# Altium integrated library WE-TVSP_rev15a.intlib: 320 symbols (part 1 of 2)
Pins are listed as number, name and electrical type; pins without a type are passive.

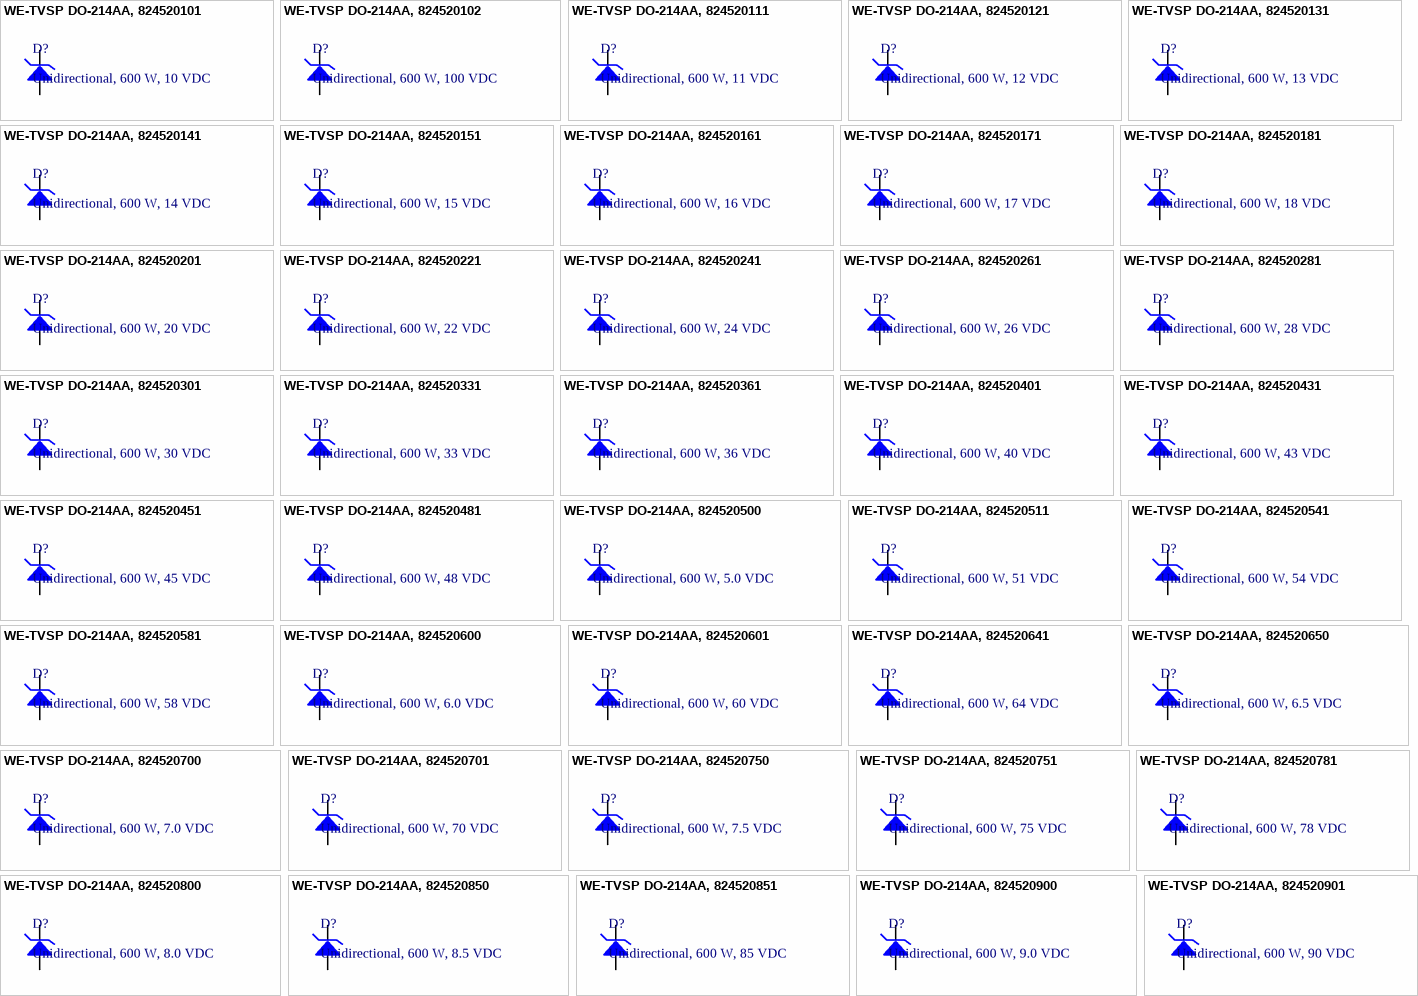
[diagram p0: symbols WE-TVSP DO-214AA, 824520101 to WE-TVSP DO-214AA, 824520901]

## WE-TVSP DO-214AA, 824520101
designator D?, comment Unidirectional, 600 W, 10 VDC
WE-TVSP Power TVS Diode, Unidirectional, 600 W, 10 VDC; partNo: 824520101; Manufacturer: Wurth Elektronik
footprint DO-214AA_Unidirectional
pins: 1, 2

## WE-TVSP DO-214AA, 824520102
designator D?, comment Unidirectional, 600 W, 100 VDC
WE-TVSP Power TVS Diode, Unidirectional, 600 W, 100 VDC; partNo: 824520102; Manufacturer: Wurth Elektronik
footprint DO-214AA_Unidirectional
pins: 1, 2

## WE-TVSP DO-214AA, 824520111
designator D?, comment Unidirectional, 600 W, 11 VDC
WE-TVSP Power TVS Diode, Unidirectional, 600 W, 11 VDC; partNo: 824520111; Manufacturer: Wurth Elektronik
footprint DO-214AA_Unidirectional
pins: 1, 2

## WE-TVSP DO-214AA, 824520121
designator D?, comment Unidirectional, 600 W, 12 VDC
WE-TVSP Power TVS Diode, Unidirectional, 600 W, 12 VDC; partNo: 824520121; Manufacturer: Wurth Elektronik
footprint DO-214AA_Unidirectional
pins: 1, 2

## WE-TVSP DO-214AA, 824520131
designator D?, comment Unidirectional, 600 W, 13 VDC
WE-TVSP Power TVS Diode, Unidirectional, 600 W, 13 VDC; partNo: 824520131; Manufacturer: Wurth Elektronik
footprint DO-214AA_Unidirectional
pins: 1, 2

## WE-TVSP DO-214AA, 824520141
designator D?, comment Unidirectional, 600 W, 14 VDC
WE-TVSP Power TVS Diode, Unidirectional, 600 W, 14 VDC; partNo: 824520141; Manufacturer: Wurth Elektronik
footprint DO-214AA_Unidirectional
pins: 1, 2

## WE-TVSP DO-214AA, 824520151
designator D?, comment Unidirectional, 600 W, 15 VDC
WE-TVSP Power TVS Diode, Unidirectional, 600 W, 15 VDC; partNo: 824520151; Manufacturer: Wurth Elektronik
footprint DO-214AA_Unidirectional
pins: 1, 2

## WE-TVSP DO-214AA, 824520161
designator D?, comment Unidirectional, 600 W, 16 VDC
WE-TVSP Power TVS Diode, Unidirectional, 600 W, 16 VDC; partNo: 824520161; Manufacturer: Wurth Elektronik
footprint DO-214AA_Unidirectional
pins: 1, 2

## WE-TVSP DO-214AA, 824520171
designator D?, comment Unidirectional, 600 W, 17 VDC
WE-TVSP Power TVS Diode, Unidirectional, 600 W, 17 VDC; partNo: 824520171; Manufacturer: Wurth Elektronik
footprint DO-214AA_Unidirectional
pins: 1, 2

## WE-TVSP DO-214AA, 824520181
designator D?, comment Unidirectional, 600 W, 18 VDC
WE-TVSP Power TVS Diode, Unidirectional, 600 W, 18 VDC; partNo: 824520181; Manufacturer: Wurth Elektronik
footprint DO-214AA_Unidirectional
pins: 1, 2

## WE-TVSP DO-214AA, 824520201
designator D?, comment Unidirectional, 600 W, 20 VDC
WE-TVSP Power TVS Diode, Unidirectional, 600 W, 20 VDC; partNo: 824520201; Manufacturer: Wurth Elektronik
footprint DO-214AA_Unidirectional
pins: 1, 2

## WE-TVSP DO-214AA, 824520221
designator D?, comment Unidirectional, 600 W, 22 VDC
WE-TVSP Power TVS Diode, Unidirectional, 600 W, 22 VDC; partNo: 824520221; Manufacturer: Wurth Elektronik
footprint DO-214AA_Unidirectional
pins: 1, 2

## WE-TVSP DO-214AA, 824520241
designator D?, comment Unidirectional, 600 W, 24 VDC
WE-TVSP Power TVS Diode, Unidirectional, 600 W, 24 VDC; partNo: 824520241; Manufacturer: Wurth Elektronik
footprint DO-214AA_Unidirectional
pins: 1, 2

## WE-TVSP DO-214AA, 824520261
designator D?, comment Unidirectional, 600 W, 26 VDC
WE-TVSP Power TVS Diode, Unidirectional, 600 W, 26 VDC; partNo: 824520261; Manufacturer: Wurth Elektronik
footprint DO-214AA_Unidirectional
pins: 1, 2

## WE-TVSP DO-214AA, 824520281
designator D?, comment Unidirectional, 600 W, 28 VDC
WE-TVSP Power TVS Diode, Unidirectional, 600 W, 28 VDC; partNo: 824520281; Manufacturer: Wurth Elektronik
footprint DO-214AA_Unidirectional
pins: 1, 2

## WE-TVSP DO-214AA, 824520301
designator D?, comment Unidirectional, 600 W, 30 VDC
WE-TVSP Power TVS Diode, Unidirectional, 600 W, 30 VDC; partNo: 824520301; Manufacturer: Wurth Elektronik
footprint DO-214AA_Unidirectional
pins: 1, 2

## WE-TVSP DO-214AA, 824520331
designator D?, comment Unidirectional, 600 W, 33 VDC
WE-TVSP Power TVS Diode, Unidirectional, 600 W, 33 VDC; partNo: 824520331; Manufacturer: Wurth Elektronik
footprint DO-214AA_Unidirectional
pins: 1, 2

## WE-TVSP DO-214AA, 824520361
designator D?, comment Unidirectional, 600 W, 36 VDC
WE-TVSP Power TVS Diode, Unidirectional, 600 W, 36 VDC; partNo: 824520361; Manufacturer: Wurth Elektronik
footprint DO-214AA_Unidirectional
pins: 1, 2

## WE-TVSP DO-214AA, 824520401
designator D?, comment Unidirectional, 600 W, 40 VDC
WE-TVSP Power TVS Diode, Unidirectional, 600 W, 40 VDC; partNo: 824520401; Manufacturer: Wurth Elektronik
footprint DO-214AA_Unidirectional
pins: 1, 2

## WE-TVSP DO-214AA, 824520431
designator D?, comment Unidirectional, 600 W, 43 VDC
WE-TVSP Power TVS Diode, Unidirectional, 600 W, 43 VDC; partNo: 824520431; Manufacturer: Wurth Elektronik
footprint DO-214AA_Unidirectional
pins: 1, 2

## WE-TVSP DO-214AA, 824520451
designator D?, comment Unidirectional, 600 W, 45 VDC
WE-TVSP Power TVS Diode, Unidirectional, 600 W, 45 VDC; partNo: 824520451; Manufacturer: Wurth Elektronik
footprint DO-214AA_Unidirectional
pins: 1, 2

## WE-TVSP DO-214AA, 824520481
designator D?, comment Unidirectional, 600 W, 48 VDC
WE-TVSP Power TVS Diode, Unidirectional, 600 W, 48 VDC; partNo: 824520481; Manufacturer: Wurth Elektronik
footprint DO-214AA_Unidirectional
pins: 1, 2

## WE-TVSP DO-214AA, 824520500
designator D?, comment Unidirectional, 600 W, 5.0 VDC
WE-TVSP Power TVS Diode, Unidirectional, 600 W, 5.0 VDC; partNo: 824520500; Manufacturer: Wurth Elektronik
footprint DO-214AA_Unidirectional
pins: 1, 2

## WE-TVSP DO-214AA, 824520511
designator D?, comment Unidirectional, 600 W, 51 VDC
WE-TVSP Power TVS Diode, Unidirectional, 600 W, 51 VDC; partNo: 824520511; Manufacturer: Wurth Elektronik
footprint DO-214AA_Unidirectional
pins: 1, 2

## WE-TVSP DO-214AA, 824520541
designator D?, comment Unidirectional, 600 W, 54 VDC
WE-TVSP Power TVS Diode, Unidirectional, 600 W, 54 VDC; partNo: 824520541; Manufacturer: Wurth Elektronik
footprint DO-214AA_Unidirectional
pins: 1, 2

## WE-TVSP DO-214AA, 824520581
designator D?, comment Unidirectional, 600 W, 58 VDC
WE-TVSP Power TVS Diode, Unidirectional, 600 W, 58 VDC; partNo: 824520581; Manufacturer: Wurth Elektronik
footprint DO-214AA_Unidirectional
pins: 1, 2

## WE-TVSP DO-214AA, 824520600
designator D?, comment Unidirectional, 600 W, 6.0 VDC
WE-TVSP Power TVS Diode, Unidirectional, 600 W, 6.0 VDC; partNo: 824520600; Manufacturer: Wurth Elektronik
footprint DO-214AA_Unidirectional
pins: 1, 2

## WE-TVSP DO-214AA, 824520601
designator D?, comment Unidirectional, 600 W, 60 VDC
WE-TVSP Power TVS Diode, Unidirectional, 600 W, 60 VDC; partNo: 824520601; Manufacturer: Wurth Elektronik
footprint DO-214AA_Unidirectional
pins: 1, 2

## WE-TVSP DO-214AA, 824520641
designator D?, comment Unidirectional, 600 W, 64 VDC
WE-TVSP Power TVS Diode, Unidirectional, 600 W, 64 VDC; partNo: 824520641; Manufacturer: Wurth Elektronik
footprint DO-214AA_Unidirectional
pins: 1, 2

## WE-TVSP DO-214AA, 824520650
designator D?, comment Unidirectional, 600 W, 6.5 VDC
WE-TVSP Power TVS Diode, Unidirectional, 600 W, 6.5 VDC; partNo: 824520650; Manufacturer: Wurth Elektronik
footprint DO-214AA_Unidirectional
pins: 1, 2

## WE-TVSP DO-214AA, 824520700
designator D?, comment Unidirectional, 600 W, 7.0 VDC
WE-TVSP Power TVS Diode, Unidirectional, 600 W, 7.0 VDC; partNo: 824520700; Manufacturer: Wurth Elektronik
footprint DO-214AA_Unidirectional
pins: 1, 2

## WE-TVSP DO-214AA, 824520701
designator D?, comment Unidirectional, 600 W, 70 VDC
WE-TVSP Power TVS Diode, Unidirectional, 600 W, 70 VDC; partNo: 824520701; Manufacturer: Wurth Elektronik
footprint DO-214AA_Unidirectional
pins: 1, 2

## WE-TVSP DO-214AA, 824520750
designator D?, comment Unidirectional, 600 W, 7.5 VDC
WE-TVSP Power TVS Diode, Unidirectional, 600 W, 7.5 VDC; partNo: 824520750; Manufacturer: Wurth Elektronik
footprint DO-214AA_Unidirectional
pins: 1, 2

## WE-TVSP DO-214AA, 824520751
designator D?, comment Unidirectional, 600 W, 75 VDC
WE-TVSP Power TVS Diode, Unidirectional, 600 W, 75 VDC; partNo: 824520751; Manufacturer: Wurth Elektronik
footprint DO-214AA_Unidirectional
pins: 1, 2

## WE-TVSP DO-214AA, 824520781
designator D?, comment Unidirectional, 600 W, 78 VDC
WE-TVSP Power TVS Diode, Unidirectional, 600 W, 78 VDC; partNo: 824520781; Manufacturer: Wurth Elektronik
footprint DO-214AA_Unidirectional
pins: 1, 2

## WE-TVSP DO-214AA, 824520800
designator D?, comment Unidirectional, 600 W, 8.0 VDC
WE-TVSP Power TVS Diode, Unidirectional, 600 W, 8.0 VDC; partNo: 824520800; Manufacturer: Wurth Elektronik
footprint DO-214AA_Unidirectional
pins: 1, 2

## WE-TVSP DO-214AA, 824520850
designator D?, comment Unidirectional, 600 W, 8.5 VDC
WE-TVSP Power TVS Diode, Unidirectional, 600 W, 8.5 VDC; partNo: 824520850; Manufacturer: Wurth Elektronik
footprint DO-214AA_Unidirectional
pins: 1, 2

## WE-TVSP DO-214AA, 824520851
designator D?, comment Unidirectional, 600 W, 85 VDC
WE-TVSP Power TVS Diode, Unidirectional, 600 W, 85 VDC; partNo: 824520851; Manufacturer: Wurth Elektronik
footprint DO-214AA_Unidirectional
pins: 1, 2

## WE-TVSP DO-214AA, 824520900
designator D?, comment Unidirectional, 600 W, 9.0 VDC
WE-TVSP Power TVS Diode, Unidirectional, 600 W, 9.0 VDC; partNo: 824520900; Manufacturer: Wurth Elektronik
footprint DO-214AA_Unidirectional
pins: 1, 2

## WE-TVSP DO-214AA, 824520901
designator D?, comment Unidirectional, 600 W, 90 VDC
WE-TVSP Power TVS Diode, Unidirectional, 600 W, 90 VDC; partNo: 824520901; Manufacturer: Wurth Elektronik
footprint DO-214AA_Unidirectional
pins: 1, 2


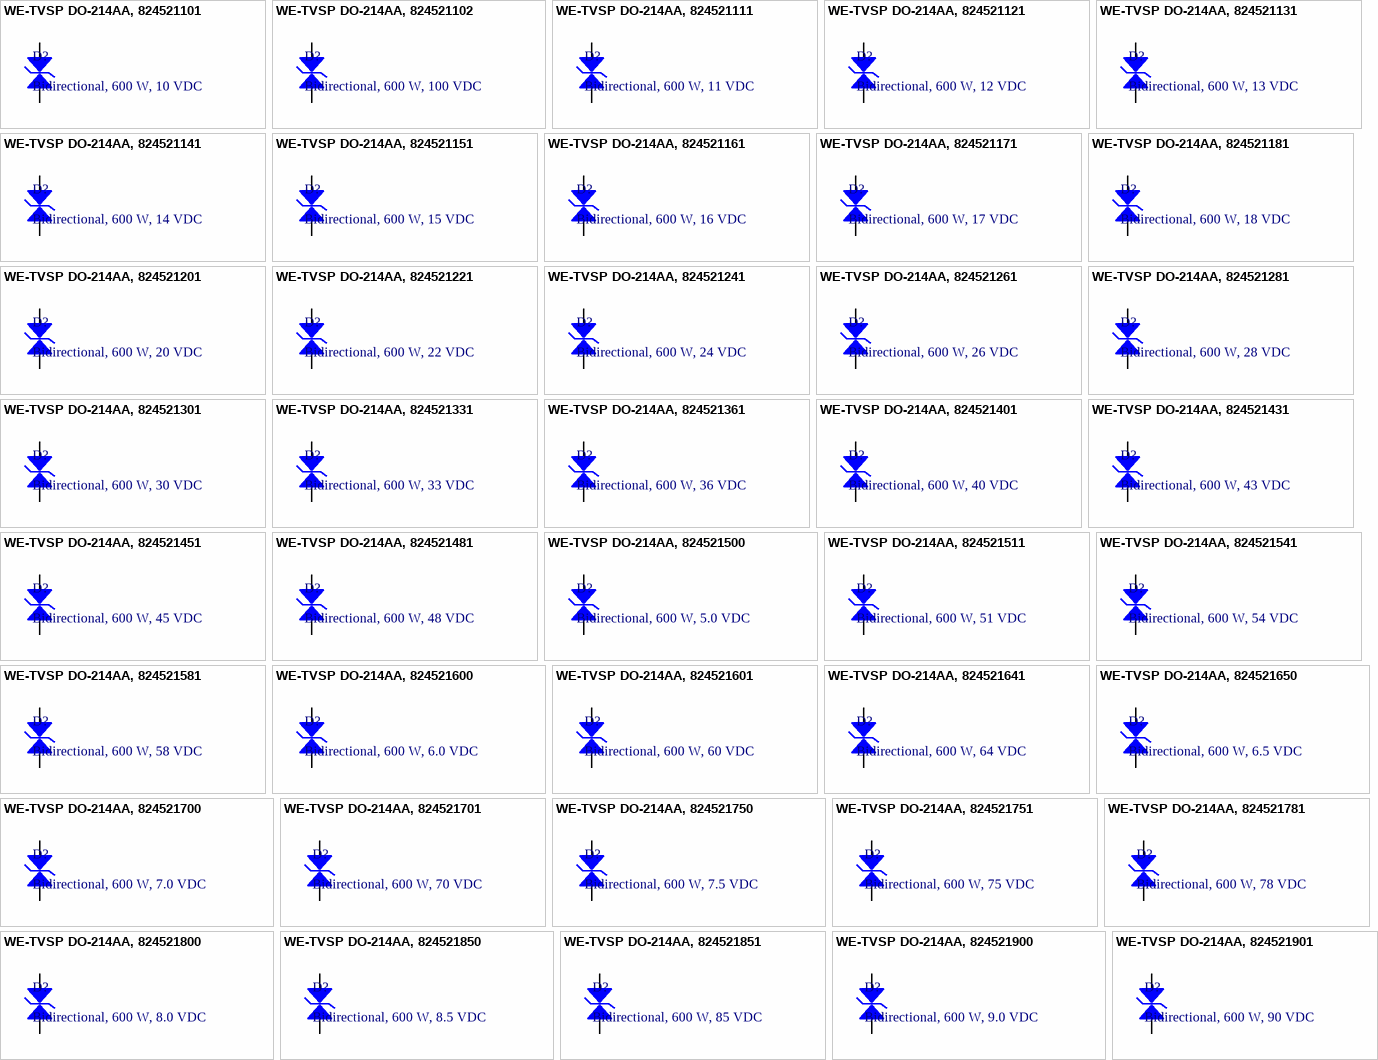
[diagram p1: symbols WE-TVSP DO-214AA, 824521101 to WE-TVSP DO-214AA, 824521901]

## WE-TVSP DO-214AA, 824521101
designator D?, comment Bidirectional, 600 W, 10 VDC
WE-TVSP Power TVS Diode, bidirectional, 600 W, 10 VDC; partNo: 824521101; Manufacturer: Wurth Elektronik
footprint DO-214AA_Bidirectional
pins: 1, 2

## WE-TVSP DO-214AA, 824521102
designator D?, comment Bidirectional, 600 W, 100 VDC
WE-TVSP Power TVS Diode, bidirectional, 600 W, 100 VDC; partNo: 824521102; Manufacturer: Wurth Elektronik
footprint DO-214AA_Bidirectional
pins: 1, 2

## WE-TVSP DO-214AA, 824521111
designator D?, comment Bidirectional, 600 W, 11 VDC
WE-TVSP Power TVS Diode, bidirectional, 600 W, 11 VDC; partNo: 824521111; Manufacturer: Wurth Elektronik
footprint DO-214AA_Bidirectional
pins: 1, 2

## WE-TVSP DO-214AA, 824521121
designator D?, comment Bidirectional, 600 W, 12 VDC
WE-TVSP Power TVS Diode, bidirectional, 600 W, 12 VDC; partNo: 824521121; Manufacturer: Wurth Elektronik
footprint DO-214AA_Bidirectional
pins: 1, 2

## WE-TVSP DO-214AA, 824521131
designator D?, comment Bidirectional, 600 W, 13 VDC
WE-TVSP Power TVS Diode, bidirectional, 600 W, 13 VDC; partNo: 824521131; Manufacturer: Wurth Elektronik
footprint DO-214AA_Bidirectional
pins: 1, 2

## WE-TVSP DO-214AA, 824521141
designator D?, comment Bidirectional, 600 W, 14 VDC
WE-TVSP Power TVS Diode, bidirectional, 600 W, 14 VDC; partNo: 824521141; Manufacturer: Wurth Elektronik
footprint DO-214AA_Bidirectional
pins: 1, 2

## WE-TVSP DO-214AA, 824521151
designator D?, comment Bidirectional, 600 W, 15 VDC
WE-TVSP Power TVS Diode, bidirectional, 600 W, 15 VDC; partNo: 824521151; Manufacturer: Wurth Elektronik
footprint DO-214AA_Bidirectional
pins: 1, 2

## WE-TVSP DO-214AA, 824521161
designator D?, comment Bidirectional, 600 W, 16 VDC
WE-TVSP Power TVS Diode, bidirectional, 600 W, 16 VDC; partNo: 824521161; Manufacturer: Wurth Elektronik
footprint DO-214AA_Bidirectional
pins: 1, 2

## WE-TVSP DO-214AA, 824521171
designator D?, comment Bidirectional, 600 W, 17 VDC
WE-TVSP Power TVS Diode, bidirectional, 600 W, 17 VDC; partNo: 824521171; Manufacturer: Wurth Elektronik
footprint DO-214AA_Bidirectional
pins: 1, 2

## WE-TVSP DO-214AA, 824521181
designator D?, comment Bidirectional, 600 W, 18 VDC
WE-TVSP Power TVS Diode, bidirectional, 600 W, 18 VDC; partNo: 824521181; Manufacturer: Wurth Elektronik
footprint DO-214AA_Bidirectional
pins: 1, 2

## WE-TVSP DO-214AA, 824521201
designator D?, comment Bidirectional, 600 W, 20 VDC
WE-TVSP Power TVS Diode, bidirectional, 600 W, 20 VDC; partNo: 824521201; Manufacturer: Wurth Elektronik
footprint DO-214AA_Bidirectional
pins: 1, 2

## WE-TVSP DO-214AA, 824521221
designator D?, comment Bidirectional, 600 W, 22 VDC
WE-TVSP Power TVS Diode, bidirectional, 600 W, 22 VDC; partNo: 824521221; Manufacturer: Wurth Elektronik
footprint DO-214AA_Bidirectional
pins: 1, 2

## WE-TVSP DO-214AA, 824521241
designator D?, comment Bidirectional, 600 W, 24 VDC
WE-TVSP Power TVS Diode, bidirectional, 600 W, 24 VDC; partNo: 824521241; Manufacturer: Wurth Elektronik
footprint DO-214AA_Bidirectional
pins: 1, 2

## WE-TVSP DO-214AA, 824521261
designator D?, comment Bidirectional, 600 W, 26 VDC
WE-TVSP Power TVS Diode, bidirectional, 600 W, 26 VDC; partNo: 824521261; Manufacturer: Wurth Elektronik
footprint DO-214AA_Bidirectional
pins: 1, 2

## WE-TVSP DO-214AA, 824521281
designator D?, comment Bidirectional, 600 W, 28 VDC
WE-TVSP Power TVS Diode, bidirectional, 600 W, 28 VDC; partNo: 824521281; Manufacturer: Wurth Elektronik
footprint DO-214AA_Bidirectional
pins: 1, 2

## WE-TVSP DO-214AA, 824521301
designator D?, comment Bidirectional, 600 W, 30 VDC
WE-TVSP Power TVS Diode, bidirectional, 600 W, 30 VDC; partNo: 824521301; Manufacturer: Wurth Elektronik
footprint DO-214AA_Bidirectional
pins: 1, 2

## WE-TVSP DO-214AA, 824521331
designator D?, comment Bidirectional, 600 W, 33 VDC
WE-TVSP Power TVS Diode, bidirectional, 600 W, 33 VDC; partNo: 824521331; Manufacturer: Wurth Elektronik
footprint DO-214AA_Bidirectional
pins: 1, 2

## WE-TVSP DO-214AA, 824521361
designator D?, comment Bidirectional, 600 W, 36 VDC
WE-TVSP Power TVS Diode, bidirectional, 600 W, 36 VDC; partNo: 824521361; Manufacturer: Wurth Elektronik
footprint DO-214AA_Bidirectional
pins: 1, 2

## WE-TVSP DO-214AA, 824521401
designator D?, comment Bidirectional, 600 W, 40 VDC
WE-TVSP Power TVS Diode, bidirectional, 600 W, 40 VDC; partNo: 824521401; Manufacturer: Wurth Elektronik
footprint DO-214AA_Bidirectional
pins: 1, 2

## WE-TVSP DO-214AA, 824521431
designator D?, comment Bidirectional, 600 W, 43 VDC
WE-TVSP Power TVS Diode, bidirectional, 600 W, 43 VDC; partNo: 824521431; Manufacturer: Wurth Elektronik
footprint DO-214AA_Bidirectional
pins: 1, 2

## WE-TVSP DO-214AA, 824521451
designator D?, comment Bidirectional, 600 W, 45 VDC
WE-TVSP Power TVS Diode, bidirectional, 600 W, 45 VDC; partNo: 824521451; Manufacturer: Wurth Elektronik
footprint DO-214AA_Bidirectional
pins: 1, 2

## WE-TVSP DO-214AA, 824521481
designator D?, comment Bidirectional, 600 W, 48 VDC
WE-TVSP Power TVS Diode, bidirectional, 600 W, 48 VDC; partNo: 824521481; Manufacturer: Wurth Elektronik
footprint DO-214AA_Bidirectional
pins: 1, 2

## WE-TVSP DO-214AA, 824521500
designator D?, comment Bidirectional, 600 W, 5.0 VDC
WE-TVSP Power TVS Diode, bidirectional, 600 W, 5.0 VDC; partNo: 824521500; Manufacturer: Wurth Elektronik
footprint DO-214AA_Bidirectional
pins: 1, 2

## WE-TVSP DO-214AA, 824521511
designator D?, comment Bidirectional, 600 W, 51 VDC
WE-TVSP Power TVS Diode, bidirectional, 600 W, 51 VDC; partNo: 824521511; Manufacturer: Wurth Elektronik
footprint DO-214AA_Bidirectional
pins: 1, 2

## WE-TVSP DO-214AA, 824521541
designator D?, comment Bidirectional, 600 W, 54 VDC
WE-TVSP Power TVS Diode, bidirectional, 600 W, 54 VDC; partNo: 824521541; Manufacturer: Wurth Elektronik
footprint DO-214AA_Bidirectional
pins: 1, 2

## WE-TVSP DO-214AA, 824521581
designator D?, comment Bidirectional, 600 W, 58 VDC
WE-TVSP Power TVS Diode, bidirectional, 600 W, 58 VDC; partNo: 824521581; Manufacturer: Wurth Elektronik
footprint DO-214AA_Bidirectional
pins: 1, 2

## WE-TVSP DO-214AA, 824521600
designator D?, comment Bidirectional, 600 W, 6.0 VDC
WE-TVSP Power TVS Diode, bidirectional, 600 W, 6.0 VDC; partNo: 824521600; Manufacturer: Wurth Elektronik
footprint DO-214AA_Bidirectional
pins: 1, 2

## WE-TVSP DO-214AA, 824521601
designator D?, comment Bidirectional, 600 W, 60 VDC
WE-TVSP Power TVS Diode, bidirectional, 600 W, 60 VDC; partNo: 824521601; Manufacturer: Wurth Elektronik
footprint DO-214AA_Bidirectional
pins: 1, 2

## WE-TVSP DO-214AA, 824521641
designator D?, comment Bidirectional, 600 W, 64 VDC
WE-TVSP Power TVS Diode, bidirectional, 600 W, 64 VDC; partNo: 824521641; Manufacturer: Wurth Elektronik
footprint DO-214AA_Bidirectional
pins: 1, 2

## WE-TVSP DO-214AA, 824521650
designator D?, comment Bidirectional, 600 W, 6.5 VDC
WE-TVSP Power TVS Diode, bidirectional, 600 W, 6.5 VDC; partNo: 824521650; Manufacturer: Wurth Elektronik
footprint DO-214AA_Bidirectional
pins: 1, 2

## WE-TVSP DO-214AA, 824521700
designator D?, comment Bidirectional, 600 W, 7.0 VDC
WE-TVSP Power TVS Diode, bidirectional, 600 W, 7.0 VDC; partNo: 824521700; Manufacturer: Wurth Elektronik
footprint DO-214AA_Bidirectional
pins: 1, 2

## WE-TVSP DO-214AA, 824521701
designator D?, comment Bidirectional, 600 W, 70 VDC
WE-TVSP Power TVS Diode, bidirectional, 600 W, 70 VDC; partNo: 824521701; Manufacturer: Wurth Elektronik
footprint DO-214AA_Bidirectional
pins: 1, 2

## WE-TVSP DO-214AA, 824521750
designator D?, comment Bidirectional, 600 W, 7.5 VDC
WE-TVSP Power TVS Diode, bidirectional, 600 W, 7.5 VDC; partNo: 824521750; Manufacturer: Wurth Elektronik
footprint DO-214AA_Bidirectional
pins: 1, 2

## WE-TVSP DO-214AA, 824521751
designator D?, comment Bidirectional, 600 W, 75 VDC
WE-TVSP Power TVS Diode, bidirectional, 600 W, 75 VDC; partNo: 824521751; Manufacturer: Wurth Elektronik
footprint DO-214AA_Bidirectional
pins: 1, 2

## WE-TVSP DO-214AA, 824521781
designator D?, comment Bidirectional, 600 W, 78 VDC
WE-TVSP Power TVS Diode, bidirectional, 600 W, 78 VDC; partNo: 824521781; Manufacturer: Wurth Elektronik
footprint DO-214AA_Bidirectional
pins: 1, 2

## WE-TVSP DO-214AA, 824521800
designator D?, comment Bidirectional, 600 W, 8.0 VDC
WE-TVSP Power TVS Diode, bidirectional, 600 W, 8.0 VDC; partNo: 824521800; Manufacturer: Wurth Elektronik
footprint DO-214AA_Bidirectional
pins: 1, 2

## WE-TVSP DO-214AA, 824521850
designator D?, comment Bidirectional, 600 W, 8.5 VDC
WE-TVSP Power TVS Diode, bidirectional, 600 W, 8.5 VDC; partNo: 824521850; Manufacturer: Wurth Elektronik
footprint DO-214AA_Bidirectional
pins: 1, 2

## WE-TVSP DO-214AA, 824521851
designator D?, comment Bidirectional, 600 W, 85 VDC
WE-TVSP Power TVS Diode, bidirectional, 600 W, 85 VDC; partNo: 824521851; Manufacturer: Wurth Elektronik
footprint DO-214AA_Bidirectional
pins: 1, 2

## WE-TVSP DO-214AA, 824521900
designator D?, comment Bidirectional, 600 W, 9.0 VDC
WE-TVSP Power TVS Diode, bidirectional, 600 W, 9.0 VDC; partNo: 824521900; Manufacturer: Wurth Elektronik
footprint DO-214AA_Bidirectional
pins: 1, 2

## WE-TVSP DO-214AA, 824521901
designator D?, comment Bidirectional, 600 W, 90 VDC
WE-TVSP Power TVS Diode, bidirectional, 600 W, 90 VDC; partNo: 824521901; Manufacturer: Wurth Elektronik
footprint DO-214AA_Bidirectional
pins: 1, 2


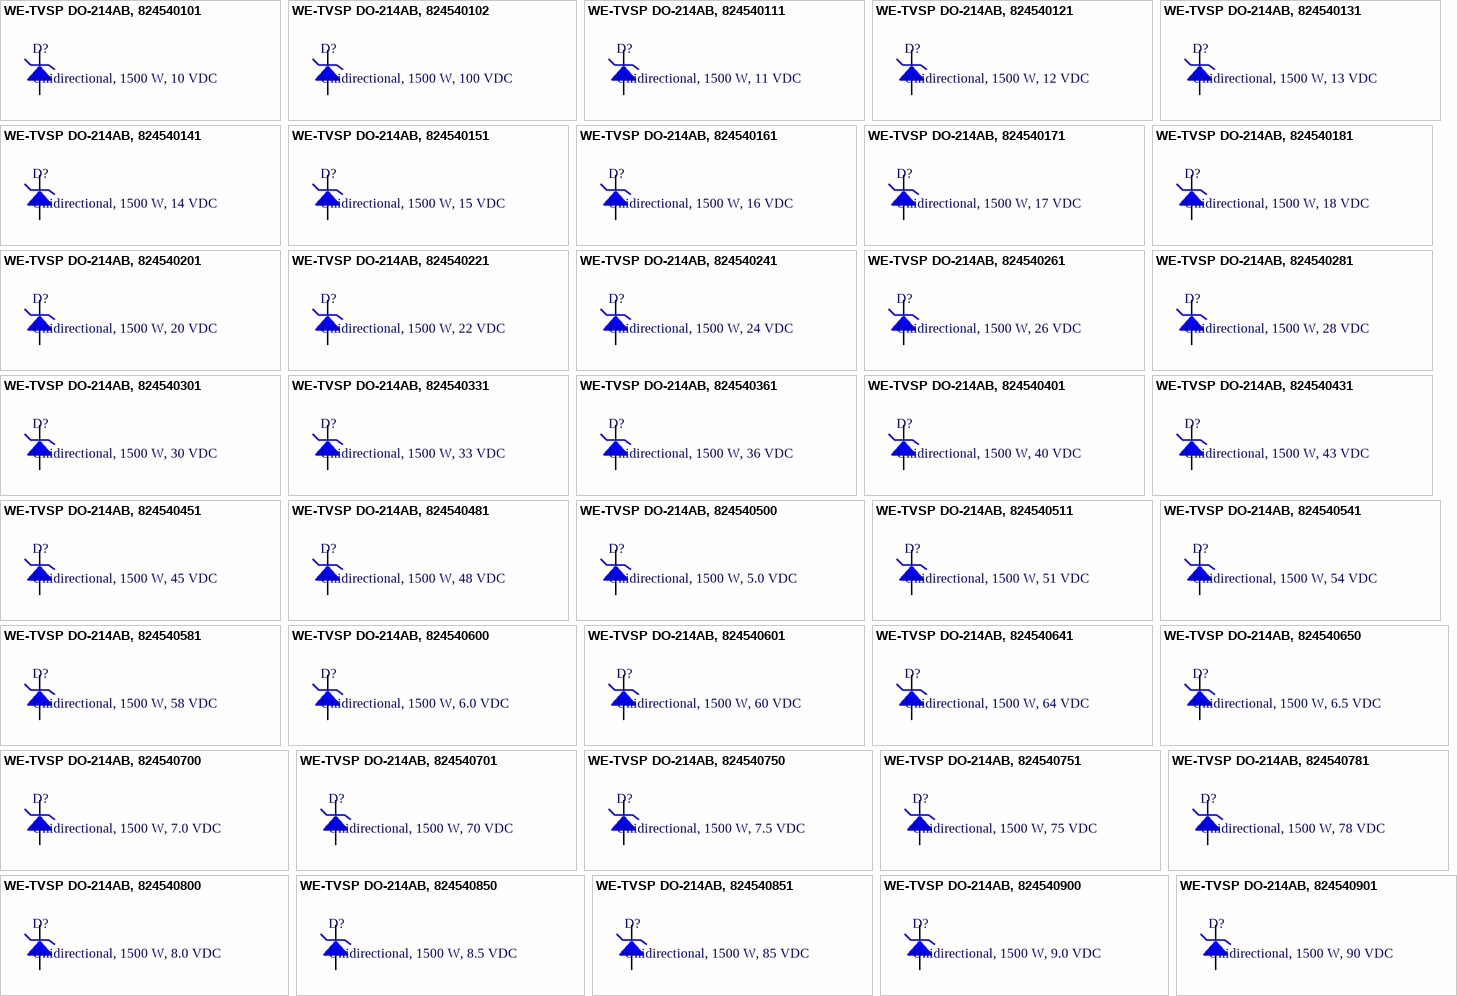
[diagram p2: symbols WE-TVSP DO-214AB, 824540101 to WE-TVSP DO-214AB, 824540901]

## WE-TVSP DO-214AB, 824540101
designator D?, comment Unidirectional, 1500 W, 10 VDC
WE-TVSP Power TVS Diode, Unidirectional, 1500 W, 10 VDC; partNo: 824540101; Manufacturer: Wurth Elektronik
footprint DO-214AB_Unidirectional
pins: 1, 2

## WE-TVSP DO-214AB, 824540102
designator D?, comment Unidirectional, 1500 W, 100 VDC
WE-TVSP Power TVS Diode, Unidirectional, 1500 W, 100 VDC; partNo: 824540102; Manufacturer: Wurth Elektronik
footprint DO-214AB_Unidirectional
pins: 1, 2

## WE-TVSP DO-214AB, 824540111
designator D?, comment Unidirectional, 1500 W, 11 VDC
WE-TVSP Power TVS Diode, Unidirectional, 1500 W, 11 VDC; partNo: 824540111; Manufacturer: Wurth Elektronik
footprint DO-214AB_Unidirectional
pins: 1, 2

## WE-TVSP DO-214AB, 824540121
designator D?, comment Unidirectional, 1500 W, 12 VDC
WE-TVSP Power TVS Diode, Unidirectional, 1500 W, 12 VDC; partNo: 824540121; Manufacturer: Wurth Elektronik
footprint DO-214AB_Unidirectional
pins: 1, 2

## WE-TVSP DO-214AB, 824540131
designator D?, comment Unidirectional, 1500 W, 13 VDC
WE-TVSP Power TVS Diode, Unidirectional, 1500 W, 13 VDC; partNo: 824540131; Manufacturer: Wurth Elektronik
footprint DO-214AB_Unidirectional
pins: 1, 2

## WE-TVSP DO-214AB, 824540141
designator D?, comment Unidirectional, 1500 W, 14 VDC
WE-TVSP Power TVS Diode, Unidirectional, 1500 W, 14 VDC; partNo: 824540141; Manufacturer: Wurth Elektronik
footprint DO-214AB_Unidirectional
pins: 1, 2

## WE-TVSP DO-214AB, 824540151
designator D?, comment Unidirectional, 1500 W, 15 VDC
WE-TVSP Power TVS Diode, Unidirectional, 1500 W, 15 VDC; partNo: 824540151; Manufacturer: Wurth Elektronik
footprint DO-214AB_Unidirectional
pins: 1, 2

## WE-TVSP DO-214AB, 824540161
designator D?, comment Unidirectional, 1500 W, 16 VDC
WE-TVSP Power TVS Diode, Unidirectional, 1500 W, 16 VDC; partNo: 824540161; Manufacturer: Wurth Elektronik
footprint DO-214AB_Unidirectional
pins: 1, 2

## WE-TVSP DO-214AB, 824540171
designator D?, comment Unidirectional, 1500 W, 17 VDC
WE-TVSP Power TVS Diode, Unidirectional, 1500 W, 17 VDC; partNo: 824540171; Manufacturer: Wurth Elektronik
footprint DO-214AB_Unidirectional
pins: 1, 2

## WE-TVSP DO-214AB, 824540181
designator D?, comment Unidirectional, 1500 W, 18 VDC
WE-TVSP Power TVS Diode, Unidirectional, 1500 W, 18 VDC; partNo: 824540181; Manufacturer: Wurth Elektronik
footprint DO-214AB_Unidirectional
pins: 1, 2

## WE-TVSP DO-214AB, 824540201
designator D?, comment Unidirectional, 1500 W, 20 VDC
WE-TVSP Power TVS Diode, Unidirectional, 1500 W, 20 VDC; partNo: 824540201; Manufacturer: Wurth Elektronik
footprint DO-214AB_Unidirectional
pins: 1, 2

## WE-TVSP DO-214AB, 824540221
designator D?, comment Unidirectional, 1500 W, 22 VDC
WE-TVSP Power TVS Diode, Unidirectional, 1500 W, 22 VDC; partNo: 824540221; Manufacturer: Wurth Elektronik
footprint DO-214AB_Unidirectional
pins: 1, 2

## WE-TVSP DO-214AB, 824540241
designator D?, comment Unidirectional, 1500 W, 24 VDC
WE-TVSP Power TVS Diode, Unidirectional, 1500 W, 24 VDC; partNo: 824540241; Manufacturer: Wurth Elektronik
footprint DO-214AB_Unidirectional
pins: 1, 2

## WE-TVSP DO-214AB, 824540261
designator D?, comment Unidirectional, 1500 W, 26 VDC
WE-TVSP Power TVS Diode, Unidirectional, 1500 W, 26 VDC; partNo: 824540261; Manufacturer: Wurth Elektronik
footprint DO-214AB_Unidirectional
pins: 1, 2

## WE-TVSP DO-214AB, 824540281
designator D?, comment Unidirectional, 1500 W, 28 VDC
WE-TVSP Power TVS Diode, Unidirectional, 1500 W, 28 VDC; partNo: 824540281; Manufacturer: Wurth Elektronik
footprint DO-214AB_Unidirectional
pins: 1, 2

## WE-TVSP DO-214AB, 824540301
designator D?, comment Unidirectional, 1500 W, 30 VDC
WE-TVSP Power TVS Diode, Unidirectional, 1500 W, 30 VDC; partNo: 824540301; Manufacturer: Wurth Elektronik
footprint DO-214AB_Unidirectional
pins: 1, 2

## WE-TVSP DO-214AB, 824540331
designator D?, comment Unidirectional, 1500 W, 33 VDC
WE-TVSP Power TVS Diode, Unidirectional, 1500 W, 33 VDC; partNo: 824540331; Manufacturer: Wurth Elektronik
footprint DO-214AB_Unidirectional
pins: 1, 2

## WE-TVSP DO-214AB, 824540361
designator D?, comment Unidirectional, 1500 W, 36 VDC
WE-TVSP Power TVS Diode, Unidirectional, 1500 W, 36 VDC; partNo: 824540361; Manufacturer: Wurth Elektronik
footprint DO-214AB_Unidirectional
pins: 1, 2

## WE-TVSP DO-214AB, 824540401
designator D?, comment Unidirectional, 1500 W, 40 VDC
WE-TVSP Power TVS Diode, Unidirectional, 1500 W, 40 VDC; partNo: 824540401; Manufacturer: Wurth Elektronik
footprint DO-214AB_Unidirectional
pins: 1, 2

## WE-TVSP DO-214AB, 824540431
designator D?, comment Unidirectional, 1500 W, 43 VDC
WE-TVSP Power TVS Diode, Unidirectional, 1500 W, 43 VDC; partNo: 824540431; Manufacturer: Wurth Elektronik
footprint DO-214AB_Unidirectional
pins: 1, 2

## WE-TVSP DO-214AB, 824540451
designator D?, comment Unidirectional, 1500 W, 45 VDC
WE-TVSP Power TVS Diode, Unidirectional, 1500 W, 45 VDC; partNo: 824540451; Manufacturer: Wurth Elektronik
footprint DO-214AB_Unidirectional
pins: 1, 2

## WE-TVSP DO-214AB, 824540481
designator D?, comment Unidirectional, 1500 W, 48 VDC
WE-TVSP Power TVS Diode, Unidirectional, 1500 W, 48 VDC; partNo: 824540481; Manufacturer: Wurth Elektronik
footprint DO-214AB_Unidirectional
pins: 1, 2

## WE-TVSP DO-214AB, 824540500
designator D?, comment Unidirectional, 1500 W, 5.0 VDC
WE-TVSP Power TVS Diode, Unidirectional, 1500 W, 5.0 VDC; partNo: 824540500; Manufacturer: Wurth Elektronik
footprint DO-214AB_Unidirectional
pins: 1, 2

## WE-TVSP DO-214AB, 824540511
designator D?, comment Unidirectional, 1500 W, 51 VDC
WE-TVSP Power TVS Diode, Unidirectional, 1500 W, 51 VDC; partNo: 824540511; Manufacturer: Wurth Elektronik
footprint DO-214AB_Unidirectional
pins: 1, 2

## WE-TVSP DO-214AB, 824540541
designator D?, comment Unidirectional, 1500 W, 54 VDC
WE-TVSP Power TVS Diode, Unidirectional, 1500 W, 54 VDC; partNo: 824540541; Manufacturer: Wurth Elektronik
footprint DO-214AB_Unidirectional
pins: 1, 2

## WE-TVSP DO-214AB, 824540581
designator D?, comment Unidirectional, 1500 W, 58 VDC
WE-TVSP Power TVS Diode, Unidirectional, 1500 W, 58 VDC; partNo: 824540581; Manufacturer: Wurth Elektronik
footprint DO-214AB_Unidirectional
pins: 1, 2

## WE-TVSP DO-214AB, 824540600
designator D?, comment Unidirectional, 1500 W, 6.0 VDC
WE-TVSP Power TVS Diode, Unidirectional, 1500 W, 6.0 VDC; partNo: 824540600; Manufacturer: Wurth Elektronik
footprint DO-214AB_Unidirectional
pins: 1, 2

## WE-TVSP DO-214AB, 824540601
designator D?, comment Unidirectional, 1500 W, 60 VDC
WE-TVSP Power TVS Diode, Unidirectional, 1500 W, 60 VDC; partNo: 824540601; Manufacturer: Wurth Elektronik
footprint DO-214AB_Unidirectional
pins: 1, 2

## WE-TVSP DO-214AB, 824540641
designator D?, comment Unidirectional, 1500 W, 64 VDC
WE-TVSP Power TVS Diode, Unidirectional, 1500 W, 64 VDC; partNo: 824540641; Manufacturer: Wurth Elektronik
footprint DO-214AB_Unidirectional
pins: 1, 2

## WE-TVSP DO-214AB, 824540650
designator D?, comment Unidirectional, 1500 W, 6.5 VDC
WE-TVSP Power TVS Diode, Unidirectional, 1500 W, 6.5 VDC; partNo: 824540650; Manufacturer: Wurth Elektronik
footprint DO-214AB_Unidirectional
pins: 1, 2

## WE-TVSP DO-214AB, 824540700
designator D?, comment Unidirectional, 1500 W, 7.0 VDC
WE-TVSP Power TVS Diode, Unidirectional, 1500 W, 7.0 VDC; partNo: 824540700; Manufacturer: Wurth Elektronik
footprint DO-214AB_Unidirectional
pins: 1, 2

## WE-TVSP DO-214AB, 824540701
designator D?, comment Unidirectional, 1500 W, 70 VDC
WE-TVSP Power TVS Diode, Unidirectional, 1500 W, 70 VDC; partNo: 824540701; Manufacturer: Wurth Elektronik
footprint DO-214AB_Unidirectional
pins: 1, 2

## WE-TVSP DO-214AB, 824540750
designator D?, comment Unidirectional, 1500 W, 7.5 VDC
WE-TVSP Power TVS Diode, Unidirectional, 1500 W, 7.5 VDC; partNo: 824540750; Manufacturer: Wurth Elektronik
footprint DO-214AB_Unidirectional
pins: 1, 2

## WE-TVSP DO-214AB, 824540751
designator D?, comment Unidirectional, 1500 W, 75 VDC
WE-TVSP Power TVS Diode, Unidirectional, 1500 W, 75 VDC; partNo: 824540751; Manufacturer: Wurth Elektronik
footprint DO-214AB_Unidirectional
pins: 1, 2

## WE-TVSP DO-214AB, 824540781
designator D?, comment Unidirectional, 1500 W, 78 VDC
WE-TVSP Power TVS Diode, Unidirectional, 1500 W, 78 VDC; partNo: 824540781; Manufacturer: Wurth Elektronik
footprint DO-214AB_Unidirectional
pins: 1, 2

## WE-TVSP DO-214AB, 824540800
designator D?, comment Unidirectional, 1500 W, 8.0 VDC
WE-TVSP Power TVS Diode, Unidirectional, 1500 W, 8.0 VDC; partNo: 824540800; Manufacturer: Wurth Elektronik
footprint DO-214AB_Unidirectional
pins: 1, 2

## WE-TVSP DO-214AB, 824540850
designator D?, comment Unidirectional, 1500 W, 8.5 VDC
WE-TVSP Power TVS Diode, Unidirectional, 1500 W, 8.5 VDC; partNo: 824540850; Manufacturer: Wurth Elektronik
footprint DO-214AB_Unidirectional
pins: 1, 2

## WE-TVSP DO-214AB, 824540851
designator D?, comment Unidirectional, 1500 W, 85 VDC
WE-TVSP Power TVS Diode, Unidirectional, 1500 W, 85 VDC; partNo: 824540851; Manufacturer: Wurth Elektronik
footprint DO-214AB_Unidirectional
pins: 1, 2

## WE-TVSP DO-214AB, 824540900
designator D?, comment Unidirectional, 1500 W, 9.0 VDC
WE-TVSP Power TVS Diode, Unidirectional, 1500 W, 9.0 VDC; partNo: 824540900; Manufacturer: Wurth Elektronik
footprint DO-214AB_Unidirectional
pins: 1, 2

## WE-TVSP DO-214AB, 824540901
designator D?, comment Unidirectional, 1500 W, 90 VDC
WE-TVSP Power TVS Diode, Unidirectional, 1500 W, 90 VDC; partNo: 824540901; Manufacturer: Wurth Elektronik
footprint DO-214AB_Unidirectional
pins: 1, 2


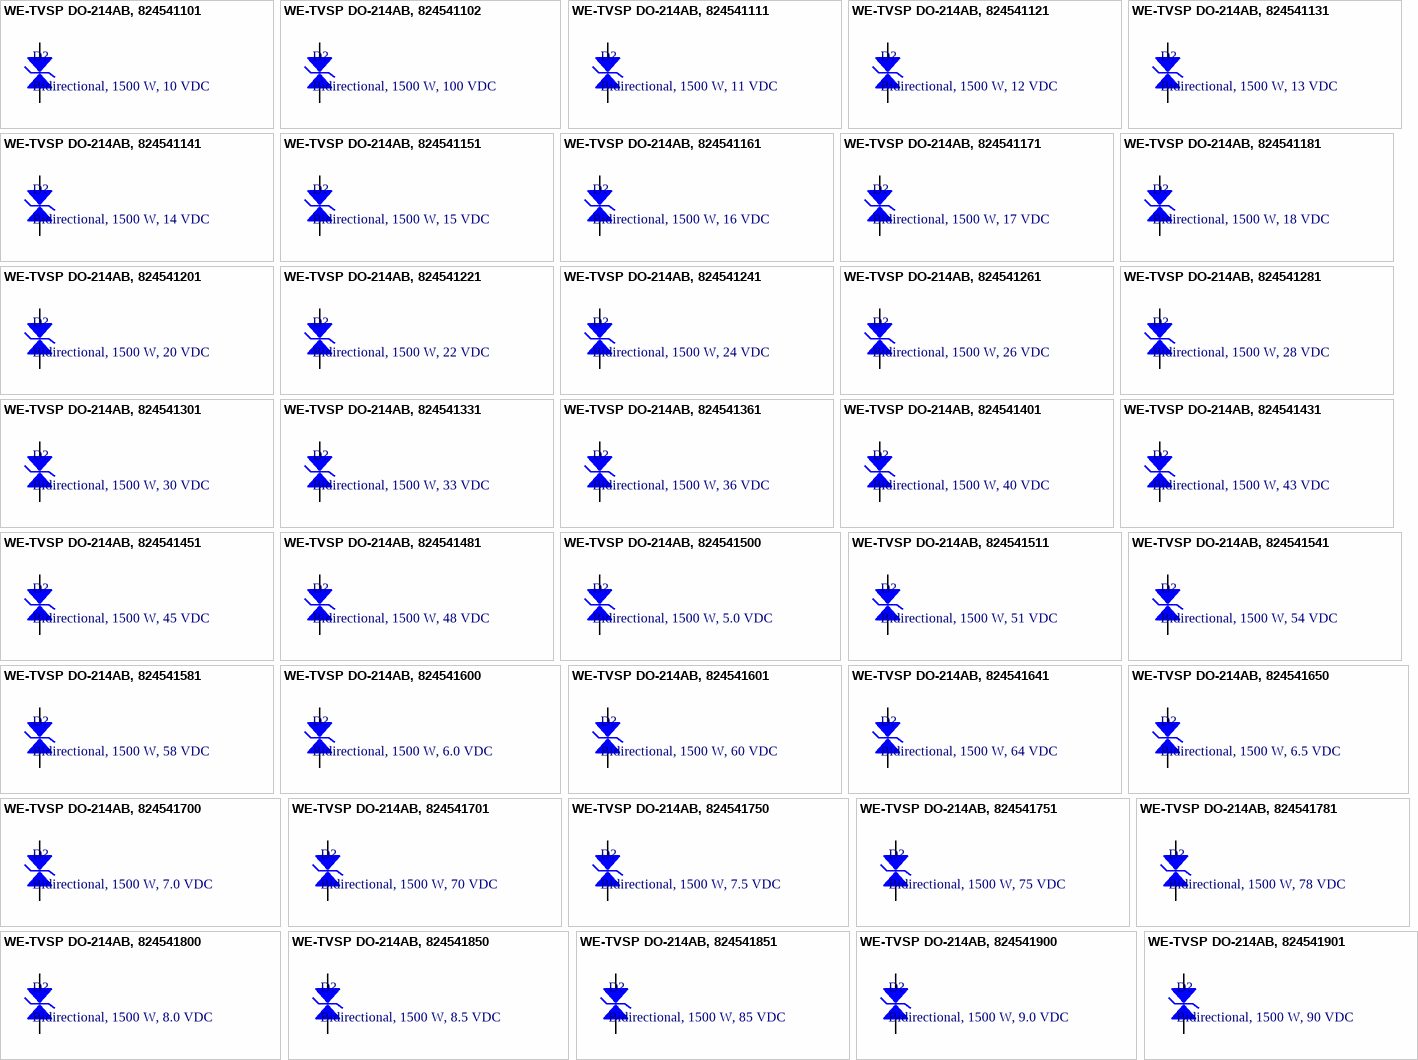
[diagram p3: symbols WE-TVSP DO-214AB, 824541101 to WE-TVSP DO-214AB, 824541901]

## WE-TVSP DO-214AB, 824541101
designator D?, comment Bidirectional, 1500 W, 10 VDC
WE-TVSP Power TVS Diode, bidirectional, 1500 W, 10 VDC; partNo: 824541101; Manufacturer: Wurth Elektronik
footprint DO-214AB_Bidirectional
pins: 1, 2

## WE-TVSP DO-214AB, 824541102
designator D?, comment Bidirectional, 1500 W, 100 VDC
WE-TVSP Power TVS Diode, bidirectional, 1500 W, 100 VDC; partNo: 824541102; Manufacturer: Wurth Elektronik
footprint DO-214AB_Bidirectional
pins: 1, 2

## WE-TVSP DO-214AB, 824541111
designator D?, comment Bidirectional, 1500 W, 11 VDC
WE-TVSP Power TVS Diode, bidirectional, 1500 W, 11 VDC; partNo: 824541111; Manufacturer: Wurth Elektronik
footprint DO-214AB_Bidirectional
pins: 1, 2

## WE-TVSP DO-214AB, 824541121
designator D?, comment Bidirectional, 1500 W, 12 VDC
WE-TVSP Power TVS Diode, bidirectional, 1500 W, 12 VDC; partNo: 824541121; Manufacturer: Wurth Elektronik
footprint DO-214AB_Bidirectional
pins: 1, 2

## WE-TVSP DO-214AB, 824541131
designator D?, comment Bidirectional, 1500 W, 13 VDC
WE-TVSP Power TVS Diode, bidirectional, 1500 W, 13 VDC; partNo: 824541131; Manufacturer: Wurth Elektronik
footprint DO-214AB_Bidirectional
pins: 1, 2

## WE-TVSP DO-214AB, 824541141
designator D?, comment Bidirectional, 1500 W, 14 VDC
WE-TVSP Power TVS Diode, bidirectional, 1500 W, 14 VDC; partNo: 824541141; Manufacturer: Wurth Elektronik
footprint DO-214AB_Bidirectional
pins: 1, 2

## WE-TVSP DO-214AB, 824541151
designator D?, comment Bidirectional, 1500 W, 15 VDC
WE-TVSP Power TVS Diode, bidirectional, 1500 W, 15 VDC; partNo: 824541151; Manufacturer: Wurth Elektronik
footprint DO-214AB_Bidirectional
pins: 1, 2

## WE-TVSP DO-214AB, 824541161
designator D?, comment Bidirectional, 1500 W, 16 VDC
WE-TVSP Power TVS Diode, bidirectional, 1500 W, 16 VDC; partNo: 824541161; Manufacturer: Wurth Elektronik
footprint DO-214AB_Bidirectional
pins: 1, 2

## WE-TVSP DO-214AB, 824541171
designator D?, comment Bidirectional, 1500 W, 17 VDC
WE-TVSP Power TVS Diode, bidirectional, 1500 W, 17 VDC; partNo: 824541171; Manufacturer: Wurth Elektronik
footprint DO-214AB_Bidirectional
pins: 1, 2

## WE-TVSP DO-214AB, 824541181
designator D?, comment Bidirectional, 1500 W, 18 VDC
WE-TVSP Power TVS Diode, bidirectional, 1500 W, 18 VDC; partNo: 824541181; Manufacturer: Wurth Elektronik
footprint DO-214AB_Bidirectional
pins: 1, 2

## WE-TVSP DO-214AB, 824541201
designator D?, comment Bidirectional, 1500 W, 20 VDC
WE-TVSP Power TVS Diode, bidirectional, 1500 W, 20 VDC; partNo: 824541201; Manufacturer: Wurth Elektronik
footprint DO-214AB_Bidirectional
pins: 1, 2

## WE-TVSP DO-214AB, 824541221
designator D?, comment Bidirectional, 1500 W, 22 VDC
WE-TVSP Power TVS Diode, bidirectional, 1500 W, 22 VDC; partNo: 824541221; Manufacturer: Wurth Elektronik
footprint DO-214AB_Bidirectional
pins: 1, 2

## WE-TVSP DO-214AB, 824541241
designator D?, comment Bidirectional, 1500 W, 24 VDC
WE-TVSP Power TVS Diode, bidirectional, 1500 W, 24 VDC; partNo: 824541241; Manufacturer: Wurth Elektronik
footprint DO-214AB_Bidirectional
pins: 1, 2

## WE-TVSP DO-214AB, 824541261
designator D?, comment Bidirectional, 1500 W, 26 VDC
WE-TVSP Power TVS Diode, bidirectional, 1500 W, 26 VDC; partNo: 824541261; Manufacturer: Wurth Elektronik
footprint DO-214AB_Bidirectional
pins: 1, 2

## WE-TVSP DO-214AB, 824541281
designator D?, comment Bidirectional, 1500 W, 28 VDC
WE-TVSP Power TVS Diode, bidirectional, 1500 W, 28 VDC; partNo: 824541281; Manufacturer: Wurth Elektronik
footprint DO-214AB_Bidirectional
pins: 1, 2

## WE-TVSP DO-214AB, 824541301
designator D?, comment Bidirectional, 1500 W, 30 VDC
WE-TVSP Power TVS Diode, bidirectional, 1500 W, 30 VDC; partNo: 824541301; Manufacturer: Wurth Elektronik
footprint DO-214AB_Bidirectional
pins: 1, 2

## WE-TVSP DO-214AB, 824541331
designator D?, comment Bidirectional, 1500 W, 33 VDC
WE-TVSP Power TVS Diode, bidirectional, 1500 W, 33 VDC; partNo: 824541331; Manufacturer: Wurth Elektronik
footprint DO-214AB_Bidirectional
pins: 1, 2

## WE-TVSP DO-214AB, 824541361
designator D?, comment Bidirectional, 1500 W, 36 VDC
WE-TVSP Power TVS Diode, bidirectional, 1500 W, 36 VDC; partNo: 824541361; Manufacturer: Wurth Elektronik
footprint DO-214AB_Bidirectional
pins: 1, 2

## WE-TVSP DO-214AB, 824541401
designator D?, comment Bidirectional, 1500 W, 40 VDC
WE-TVSP Power TVS Diode, bidirectional, 1500 W, 40 VDC; partNo: 824541401; Manufacturer: Wurth Elektronik
footprint DO-214AB_Bidirectional
pins: 1, 2

## WE-TVSP DO-214AB, 824541431
designator D?, comment Bidirectional, 1500 W, 43 VDC
WE-TVSP Power TVS Diode, bidirectional, 1500 W, 43 VDC; partNo: 824541431; Manufacturer: Wurth Elektronik
footprint DO-214AB_Bidirectional
pins: 1, 2

## WE-TVSP DO-214AB, 824541451
designator D?, comment Bidirectional, 1500 W, 45 VDC
WE-TVSP Power TVS Diode, bidirectional, 1500 W, 45 VDC; partNo: 824541451; Manufacturer: Wurth Elektronik
footprint DO-214AB_Bidirectional
pins: 1, 2

## WE-TVSP DO-214AB, 824541481
designator D?, comment Bidirectional, 1500 W, 48 VDC
WE-TVSP Power TVS Diode, bidirectional, 1500 W, 48 VDC; partNo: 824541481; Manufacturer: Wurth Elektronik
footprint DO-214AB_Bidirectional
pins: 1, 2

## WE-TVSP DO-214AB, 824541500
designator D?, comment Bidirectional, 1500 W, 5.0 VDC
WE-TVSP Power TVS Diode, bidirectional, 1500 W, 5.0 VDC; partNo: 824541500; Manufacturer: Wurth Elektronik
footprint DO-214AB_Bidirectional
pins: 1, 2

## WE-TVSP DO-214AB, 824541511
designator D?, comment Bidirectional, 1500 W, 51 VDC
WE-TVSP Power TVS Diode, bidirectional, 1500 W, 51 VDC; partNo: 824541511; Manufacturer: Wurth Elektronik
footprint DO-214AB_Bidirectional
pins: 1, 2

## WE-TVSP DO-214AB, 824541541
designator D?, comment Bidirectional, 1500 W, 54 VDC
WE-TVSP Power TVS Diode, bidirectional, 1500 W, 54 VDC; partNo: 824541541; Manufacturer: Wurth Elektronik
footprint DO-214AB_Bidirectional
pins: 1, 2

## WE-TVSP DO-214AB, 824541581
designator D?, comment Bidirectional, 1500 W, 58 VDC
WE-TVSP Power TVS Diode, bidirectional, 1500 W, 58 VDC; partNo: 824541581; Manufacturer: Wurth Elektronik
footprint DO-214AB_Bidirectional
pins: 1, 2

## WE-TVSP DO-214AB, 824541600
designator D?, comment Bidirectional, 1500 W, 6.0 VDC
WE-TVSP Power TVS Diode, bidirectional, 1500 W, 6.0 VDC; partNo: 824541600; Manufacturer: Wurth Elektronik
footprint DO-214AB_Bidirectional
pins: 1, 2

## WE-TVSP DO-214AB, 824541601
designator D?, comment Bidirectional, 1500 W, 60 VDC
WE-TVSP Power TVS Diode, bidirectional, 1500 W, 60 VDC; partNo: 824541601; Manufacturer: Wurth Elektronik
footprint DO-214AB_Bidirectional
pins: 1, 2

## WE-TVSP DO-214AB, 824541641
designator D?, comment Bidirectional, 1500 W, 64 VDC
WE-TVSP Power TVS Diode, bidirectional, 1500 W, 64 VDC; partNo: 824541641; Manufacturer: Wurth Elektronik
footprint DO-214AB_Bidirectional
pins: 1, 2

## WE-TVSP DO-214AB, 824541650
designator D?, comment Bidirectional, 1500 W, 6.5 VDC
WE-TVSP Power TVS Diode, bidirectional, 1500 W, 6.5 VDC; partNo: 824541650; Manufacturer: Wurth Elektronik
footprint DO-214AB_Bidirectional
pins: 1, 2

## WE-TVSP DO-214AB, 824541700
designator D?, comment Bidirectional, 1500 W, 7.0 VDC
WE-TVSP Power TVS Diode, bidirectional, 1500 W, 7.0 VDC; partNo: 824541700; Manufacturer: Wurth Elektronik
footprint DO-214AB_Bidirectional
pins: 1, 2

## WE-TVSP DO-214AB, 824541701
designator D?, comment Bidirectional, 1500 W, 70 VDC
WE-TVSP Power TVS Diode, bidirectional, 1500 W, 70 VDC; partNo: 824541701; Manufacturer: Wurth Elektronik
footprint DO-214AB_Bidirectional
pins: 1, 2

## WE-TVSP DO-214AB, 824541750
designator D?, comment Bidirectional, 1500 W, 7.5 VDC
WE-TVSP Power TVS Diode, bidirectional, 1500 W, 7.5 VDC; partNo: 824541750; Manufacturer: Wurth Elektronik
footprint DO-214AB_Bidirectional
pins: 1, 2

## WE-TVSP DO-214AB, 824541751
designator D?, comment Bidirectional, 1500 W, 75 VDC
WE-TVSP Power TVS Diode, bidirectional, 1500 W, 75 VDC; partNo: 824541751; Manufacturer: Wurth Elektronik
footprint DO-214AB_Bidirectional
pins: 1, 2

## WE-TVSP DO-214AB, 824541781
designator D?, comment Bidirectional, 1500 W, 78 VDC
WE-TVSP Power TVS Diode, bidirectional, 1500 W, 78 VDC; partNo: 824541781; Manufacturer: Wurth Elektronik
footprint DO-214AB_Bidirectional
pins: 1, 2

## WE-TVSP DO-214AB, 824541800
designator D?, comment Bidirectional, 1500 W, 8.0 VDC
WE-TVSP Power TVS Diode, bidirectional, 1500 W, 8.0 VDC; partNo: 824541800; Manufacturer: Wurth Elektronik
footprint DO-214AB_Bidirectional
pins: 1, 2

## WE-TVSP DO-214AB, 824541850
designator D?, comment Bidirectional, 1500 W, 8.5 VDC
WE-TVSP Power TVS Diode, bidirectional, 1500 W, 8.5 VDC; partNo: 824541850; Manufacturer: Wurth Elektronik
footprint DO-214AB_Bidirectional
pins: 1, 2

## WE-TVSP DO-214AB, 824541851
designator D?, comment Bidirectional, 1500 W, 85 VDC
WE-TVSP Power TVS Diode, bidirectional, 1500 W, 85 VDC; partNo: 824541851; Manufacturer: Wurth Elektronik
footprint DO-214AB_Bidirectional
pins: 1, 2

## WE-TVSP DO-214AB, 824541900
designator D?, comment Bidirectional, 1500 W, 9.0 VDC
WE-TVSP Power TVS Diode, bidirectional, 1500 W, 9.0 VDC; partNo: 824541900; Manufacturer: Wurth Elektronik
footprint DO-214AB_Bidirectional
pins: 1, 2

## WE-TVSP DO-214AB, 824541901
designator D?, comment Bidirectional, 1500 W, 90 VDC
WE-TVSP Power TVS Diode, bidirectional, 1500 W, 90 VDC; partNo: 824541901; Manufacturer: Wurth Elektronik
footprint DO-214AB_Bidirectional
pins: 1, 2


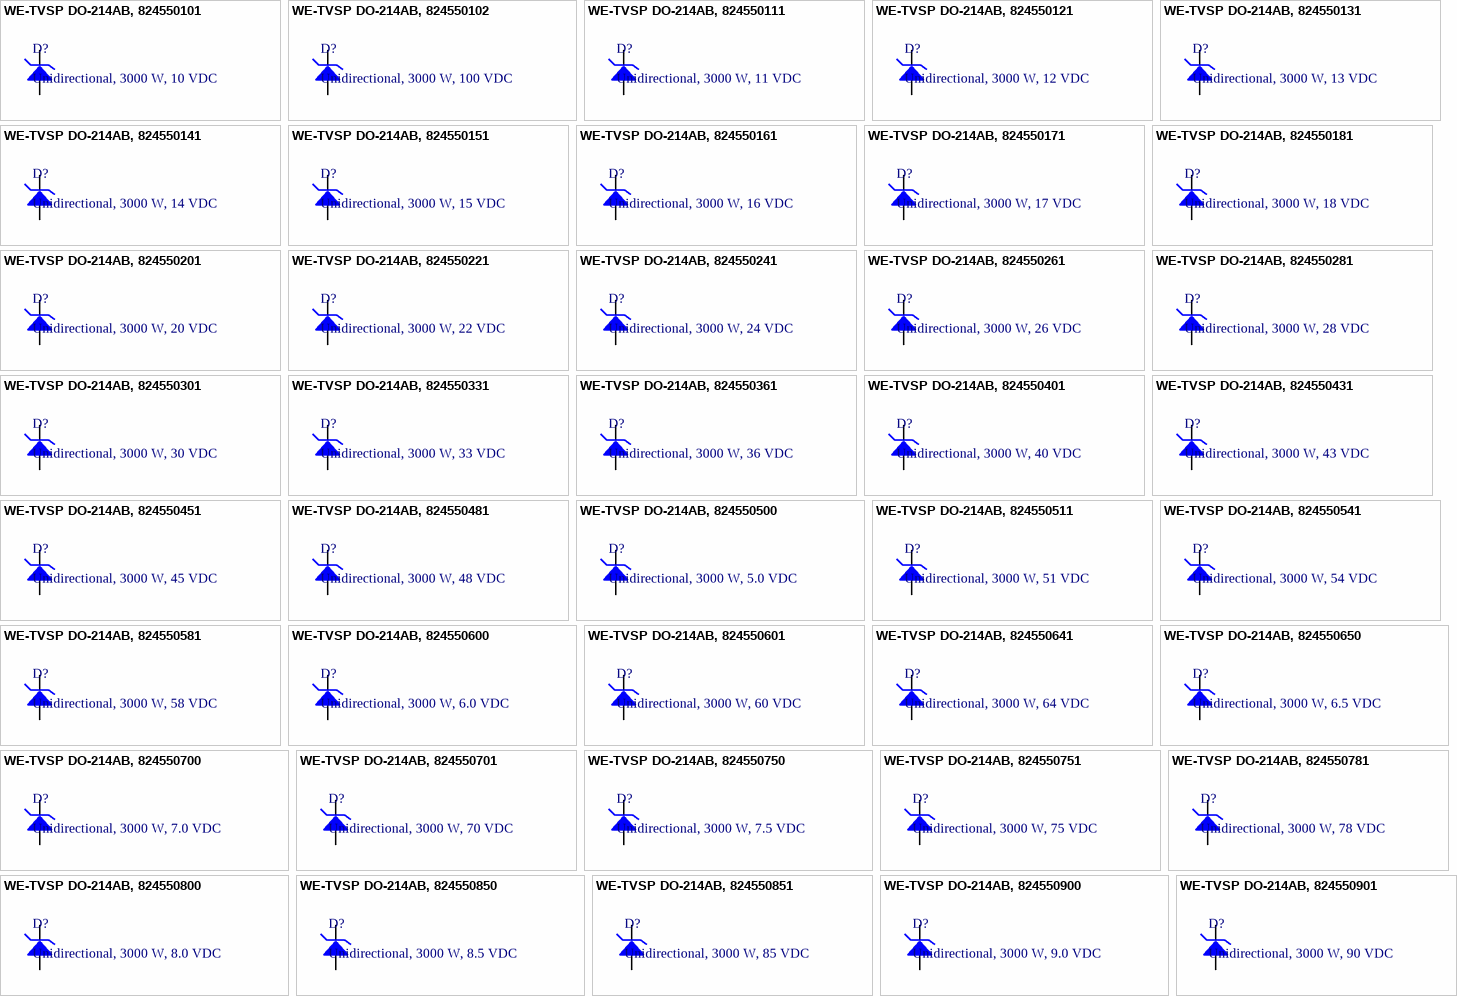
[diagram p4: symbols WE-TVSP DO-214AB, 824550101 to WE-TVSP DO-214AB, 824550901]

## WE-TVSP DO-214AB, 824550101
designator D?, comment Unidirectional, 3000 W, 10 VDC
WE-TVSP Power TVS Diode, Unidirectional, 3000 W, 10 VDC; partNo: 824550101; Manufacturer: Wurth Elektronik
footprint DO-214AB_Bidirectional
pins: 1, 2

## WE-TVSP DO-214AB, 824550102
designator D?, comment Unidirectional, 3000 W, 100 VDC
WE-TVSP Power TVS Diode, Unidirectional, 3000 W, 100 VDC; partNo: 824550102; Manufacturer: Wurth Elektronik
footprint DO-214AB_Bidirectional
pins: 1, 2

## WE-TVSP DO-214AB, 824550111
designator D?, comment Unidirectional, 3000 W, 11 VDC
WE-TVSP Power TVS Diode, Unidirectional, 3000 W, 11 VDC; partNo: 824550111; Manufacturer: Wurth Elektronik
footprint DO-214AB_Bidirectional
pins: 1, 2

## WE-TVSP DO-214AB, 824550121
designator D?, comment Unidirectional, 3000 W, 12 VDC
WE-TVSP Power TVS Diode, Unidirectional, 3000 W, 12 VDC; partNo: 824550121; Manufacturer: Wurth Elektronik
footprint DO-214AB_Bidirectional
pins: 1, 2

## WE-TVSP DO-214AB, 824550131
designator D?, comment Unidirectional, 3000 W, 13 VDC
WE-TVSP Power TVS Diode, Unidirectional, 3000 W, 13 VDC; partNo: 824550131; Manufacturer: Wurth Elektronik
footprint DO-214AB_Bidirectional
pins: 1, 2

## WE-TVSP DO-214AB, 824550141
designator D?, comment Unidirectional, 3000 W, 14 VDC
WE-TVSP Power TVS Diode, Unidirectional, 3000 W, 14 VDC; partNo: 824550141; Manufacturer: Wurth Elektronik
footprint DO-214AB_Bidirectional
pins: 1, 2

## WE-TVSP DO-214AB, 824550151
designator D?, comment Unidirectional, 3000 W, 15 VDC
WE-TVSP Power TVS Diode, Unidirectional, 3000 W, 15 VDC; partNo: 824550151; Manufacturer: Wurth Elektronik
footprint DO-214AB_Bidirectional
pins: 1, 2

## WE-TVSP DO-214AB, 824550161
designator D?, comment Unidirectional, 3000 W, 16 VDC
WE-TVSP Power TVS Diode, Unidirectional, 3000 W, 16 VDC; partNo: 824550161; Manufacturer: Wurth Elektronik
footprint DO-214AB_Bidirectional
pins: 1, 2

## WE-TVSP DO-214AB, 824550171
designator D?, comment Unidirectional, 3000 W, 17 VDC
WE-TVSP Power TVS Diode, Unidirectional, 3000 W, 17 VDC; partNo: 824550171; Manufacturer: Wurth Elektronik
footprint DO-214AB_Bidirectional
pins: 1, 2

## WE-TVSP DO-214AB, 824550181
designator D?, comment Unidirectional, 3000 W, 18 VDC
WE-TVSP Power TVS Diode, Unidirectional, 3000 W, 18 VDC; partNo: 824550181; Manufacturer: Wurth Elektronik
footprint DO-214AB_Bidirectional
pins: 1, 2

## WE-TVSP DO-214AB, 824550201
designator D?, comment Unidirectional, 3000 W, 20 VDC
WE-TVSP Power TVS Diode, Unidirectional, 3000 W, 20 VDC; partNo: 824550201; Manufacturer: Wurth Elektronik
footprint DO-214AB_Bidirectional
pins: 1, 2

## WE-TVSP DO-214AB, 824550221
designator D?, comment Unidirectional, 3000 W, 22 VDC
WE-TVSP Power TVS Diode, Unidirectional, 3000 W, 22 VDC; partNo: 824550221; Manufacturer: Wurth Elektronik
footprint DO-214AB_Bidirectional
pins: 1, 2

## WE-TVSP DO-214AB, 824550241
designator D?, comment Unidirectional, 3000 W, 24 VDC
WE-TVSP Power TVS Diode, Unidirectional, 3000 W, 24 VDC; partNo: 824550241; Manufacturer: Wurth Elektronik
footprint DO-214AB_Bidirectional
pins: 1, 2

## WE-TVSP DO-214AB, 824550261
designator D?, comment Unidirectional, 3000 W, 26 VDC
WE-TVSP Power TVS Diode, Unidirectional, 3000 W, 26 VDC; partNo: 824550261; Manufacturer: Wurth Elektronik
footprint DO-214AB_Bidirectional
pins: 1, 2

## WE-TVSP DO-214AB, 824550281
designator D?, comment Unidirectional, 3000 W, 28 VDC
WE-TVSP Power TVS Diode, Unidirectional, 3000 W, 28 VDC; partNo: 824550281; Manufacturer: Wurth Elektronik
footprint DO-214AB_Bidirectional
pins: 1, 2

## WE-TVSP DO-214AB, 824550301
designator D?, comment Unidirectional, 3000 W, 30 VDC
WE-TVSP Power TVS Diode, Unidirectional, 3000 W, 30 VDC; partNo: 824550301; Manufacturer: Wurth Elektronik
footprint DO-214AB_Bidirectional
pins: 1, 2

## WE-TVSP DO-214AB, 824550331
designator D?, comment Unidirectional, 3000 W, 33 VDC
WE-TVSP Power TVS Diode, Unidirectional, 3000 W, 33 VDC; partNo: 824550331; Manufacturer: Wurth Elektronik
footprint DO-214AB_Bidirectional
pins: 1, 2

## WE-TVSP DO-214AB, 824550361
designator D?, comment Unidirectional, 3000 W, 36 VDC
WE-TVSP Power TVS Diode, Unidirectional, 3000 W, 36 VDC; partNo: 824550361; Manufacturer: Wurth Elektronik
footprint DO-214AB_Bidirectional
pins: 1, 2

## WE-TVSP DO-214AB, 824550401
designator D?, comment Unidirectional, 3000 W, 40 VDC
WE-TVSP Power TVS Diode, Unidirectional, 3000 W, 40 VDC; partNo: 824550401; Manufacturer: Wurth Elektronik
footprint DO-214AB_Bidirectional
pins: 1, 2

## WE-TVSP DO-214AB, 824550431
designator D?, comment Unidirectional, 3000 W, 43 VDC
WE-TVSP Power TVS Diode, Unidirectional, 3000 W, 43 VDC; partNo: 824550431; Manufacturer: Wurth Elektronik
footprint DO-214AB_Bidirectional
pins: 1, 2

## WE-TVSP DO-214AB, 824550451
designator D?, comment Unidirectional, 3000 W, 45 VDC
WE-TVSP Power TVS Diode, Unidirectional, 3000 W, 45 VDC; partNo: 824550451; Manufacturer: Wurth Elektronik
footprint DO-214AB_Bidirectional
pins: 1, 2

## WE-TVSP DO-214AB, 824550481
designator D?, comment Unidirectional, 3000 W, 48 VDC
WE-TVSP Power TVS Diode, Unidirectional, 3000 W, 48 VDC; partNo: 824550481; Manufacturer: Wurth Elektronik
footprint DO-214AB_Bidirectional
pins: 1, 2

## WE-TVSP DO-214AB, 824550500
designator D?, comment Unidirectional, 3000 W, 5.0 VDC
WE-TVSP Power TVS Diode, Unidirectional, 3000 W, 5.0 VDC; partNo: 824550500; Manufacturer: Wurth Elektronik
footprint DO-214AB_Bidirectional
pins: 1, 2

## WE-TVSP DO-214AB, 824550511
designator D?, comment Unidirectional, 3000 W, 51 VDC
WE-TVSP Power TVS Diode, Unidirectional, 3000 W, 51 VDC; partNo: 824550511; Manufacturer: Wurth Elektronik
footprint DO-214AB_Bidirectional
pins: 1, 2

## WE-TVSP DO-214AB, 824550541
designator D?, comment Unidirectional, 3000 W, 54 VDC
WE-TVSP Power TVS Diode, Unidirectional, 3000 W, 54 VDC; partNo: 824550541; Manufacturer: Wurth Elektronik
footprint DO-214AB_Bidirectional
pins: 1, 2

## WE-TVSP DO-214AB, 824550581
designator D?, comment Unidirectional, 3000 W, 58 VDC
WE-TVSP Power TVS Diode, Unidirectional, 3000 W, 58 VDC; partNo: 824550581; Manufacturer: Wurth Elektronik
footprint DO-214AB_Bidirectional
pins: 1, 2

## WE-TVSP DO-214AB, 824550600
designator D?, comment Unidirectional, 3000 W, 6.0 VDC
WE-TVSP Power TVS Diode, Unidirectional, 3000 W, 6.0 VDC; partNo: 824550600; Manufacturer: Wurth Elektronik
footprint DO-214AB_Bidirectional
pins: 1, 2

## WE-TVSP DO-214AB, 824550601
designator D?, comment Unidirectional, 3000 W, 60 VDC
WE-TVSP Power TVS Diode, Unidirectional, 3000 W, 60 VDC; partNo: 824550601; Manufacturer: Wurth Elektronik
footprint DO-214AB_Bidirectional
pins: 1, 2

## WE-TVSP DO-214AB, 824550641
designator D?, comment Unidirectional, 3000 W, 64 VDC
WE-TVSP Power TVS Diode, Unidirectional, 3000 W, 64 VDC; partNo: 824550641; Manufacturer: Wurth Elektronik
footprint DO-214AB_Bidirectional
pins: 1, 2

## WE-TVSP DO-214AB, 824550650
designator D?, comment Unidirectional, 3000 W, 6.5 VDC
WE-TVSP Power TVS Diode, Unidirectional, 3000 W, 6.5 VDC; partNo: 824550650; Manufacturer: Wurth Elektronik
footprint DO-214AB_Bidirectional
pins: 1, 2

## WE-TVSP DO-214AB, 824550700
designator D?, comment Unidirectional, 3000 W, 7.0 VDC
WE-TVSP Power TVS Diode, Unidirectional, 3000 W, 7.0 VDC; partNo: 824550700; Manufacturer: Wurth Elektronik
footprint DO-214AB_Bidirectional
pins: 1, 2

## WE-TVSP DO-214AB, 824550701
designator D?, comment Unidirectional, 3000 W, 70 VDC
WE-TVSP Power TVS Diode, Unidirectional, 3000 W, 70 VDC; partNo: 824550701; Manufacturer: Wurth Elektronik
footprint DO-214AB_Bidirectional
pins: 1, 2

## WE-TVSP DO-214AB, 824550750
designator D?, comment Unidirectional, 3000 W, 7.5 VDC
WE-TVSP Power TVS Diode, Unidirectional, 3000 W, 7.5 VDC; partNo: 824550750; Manufacturer: Wurth Elektronik
footprint DO-214AB_Bidirectional
pins: 1, 2

## WE-TVSP DO-214AB, 824550751
designator D?, comment Unidirectional, 3000 W, 75 VDC
WE-TVSP Power TVS Diode, Unidirectional, 3000 W, 75 VDC; partNo: 824550751; Manufacturer: Wurth Elektronik
footprint DO-214AB_Bidirectional
pins: 1, 2

## WE-TVSP DO-214AB, 824550781
designator D?, comment Unidirectional, 3000 W, 78 VDC
WE-TVSP Power TVS Diode, Unidirectional, 3000 W, 78 VDC; partNo: 824550781; Manufacturer: Wurth Elektronik
footprint DO-214AB_Bidirectional
pins: 1, 2

## WE-TVSP DO-214AB, 824550800
designator D?, comment Unidirectional, 3000 W, 8.0 VDC
WE-TVSP Power TVS Diode, Unidirectional, 3000 W, 8.0 VDC; partNo: 824550800; Manufacturer: Wurth Elektronik
footprint DO-214AB_Bidirectional
pins: 1, 2

## WE-TVSP DO-214AB, 824550850
designator D?, comment Unidirectional, 3000 W, 8.5 VDC
WE-TVSP Power TVS Diode, Unidirectional, 3000 W, 8.5 VDC; partNo: 824550850; Manufacturer: Wurth Elektronik
footprint DO-214AB_Bidirectional
pins: 1, 2

## WE-TVSP DO-214AB, 824550851
designator D?, comment Unidirectional, 3000 W, 85 VDC
WE-TVSP Power TVS Diode, Unidirectional, 3000 W, 85 VDC; partNo: 824550851; Manufacturer: Wurth Elektronik
footprint DO-214AB_Bidirectional
pins: 1, 2

## WE-TVSP DO-214AB, 824550900
designator D?, comment Unidirectional, 3000 W, 9.0 VDC
WE-TVSP Power TVS Diode, Unidirectional, 3000 W, 9.0 VDC; partNo: 824550900; Manufacturer: Wurth Elektronik
footprint DO-214AB_Bidirectional
pins: 1, 2

## WE-TVSP DO-214AB, 824550901
designator D?, comment Unidirectional, 3000 W, 90 VDC
WE-TVSP Power TVS Diode, Unidirectional, 3000 W, 90 VDC; partNo: 824550901; Manufacturer: Wurth Elektronik
footprint DO-214AB_Bidirectional
pins: 1, 2


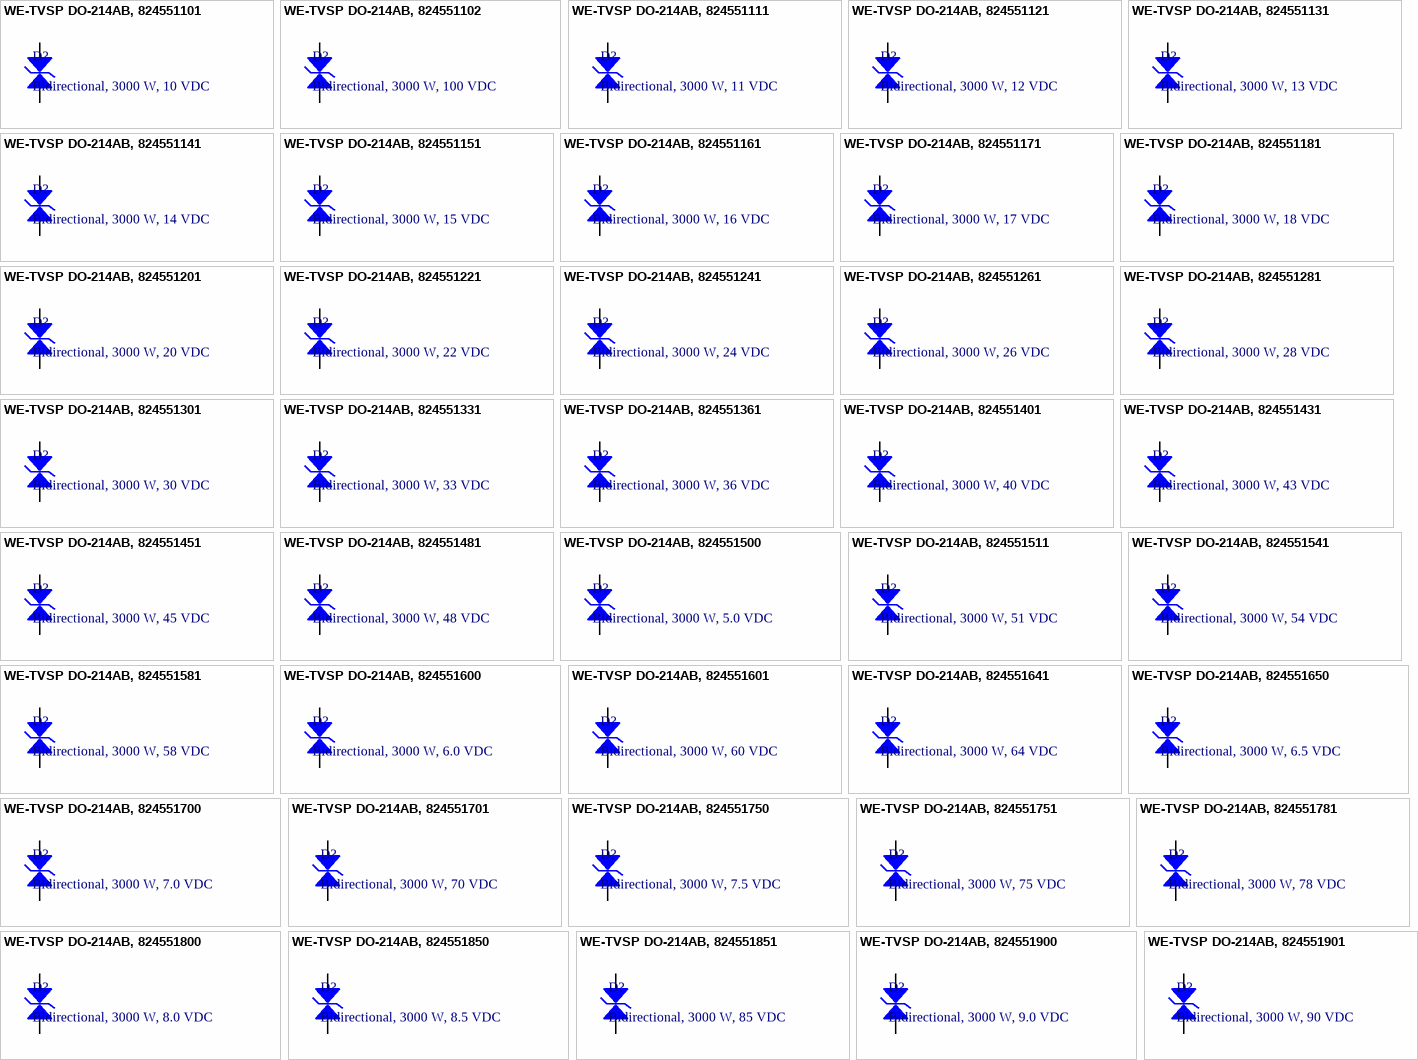
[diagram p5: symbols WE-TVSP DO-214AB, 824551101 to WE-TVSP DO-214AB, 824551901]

## WE-TVSP DO-214AB, 824551101
designator D?, comment Bidirectional, 3000 W, 10 VDC
WE-TVSP Power TVS Diode, bidirectional, 3000 W, 10 VDC; partNo: 824551101; Manufacturer: Wurth Elektronik
footprint DO-214AB_Bidirectional
pins: 1, 2

## WE-TVSP DO-214AB, 824551102
designator D?, comment Bidirectional, 3000 W, 100 VDC
WE-TVSP Power TVS Diode, bidirectional, 3000 W, 100 VDC; partNo: 824551102; Manufacturer: Wurth Elektronik
footprint DO-214AB_Bidirectional
pins: 1, 2

## WE-TVSP DO-214AB, 824551111
designator D?, comment Bidirectional, 3000 W, 11 VDC
WE-TVSP Power TVS Diode, bidirectional, 3000 W, 11 VDC; partNo: 824551111; Manufacturer: Wurth Elektronik
footprint DO-214AB_Bidirectional
pins: 1, 2

## WE-TVSP DO-214AB, 824551121
designator D?, comment Bidirectional, 3000 W, 12 VDC
WE-TVSP Power TVS Diode, bidirectional, 3000 W, 12 VDC; partNo: 824551121; Manufacturer: Wurth Elektronik
footprint DO-214AB_Bidirectional
pins: 1, 2

## WE-TVSP DO-214AB, 824551131
designator D?, comment Bidirectional, 3000 W, 13 VDC
WE-TVSP Power TVS Diode, bidirectional, 3000 W, 13 VDC; partNo: 824551131; Manufacturer: Wurth Elektronik
footprint DO-214AB_Bidirectional
pins: 1, 2

## WE-TVSP DO-214AB, 824551141
designator D?, comment Bidirectional, 3000 W, 14 VDC
WE-TVSP Power TVS Diode, bidirectional, 3000 W, 14 VDC; partNo: 824551141; Manufacturer: Wurth Elektronik
footprint DO-214AB_Bidirectional
pins: 1, 2

## WE-TVSP DO-214AB, 824551151
designator D?, comment Bidirectional, 3000 W, 15 VDC
WE-TVSP Power TVS Diode, bidirectional, 3000 W, 15 VDC; partNo: 824551151; Manufacturer: Wurth Elektronik
footprint DO-214AB_Bidirectional
pins: 1, 2

## WE-TVSP DO-214AB, 824551161
designator D?, comment Bidirectional, 3000 W, 16 VDC
WE-TVSP Power TVS Diode, bidirectional, 3000 W, 16 VDC; partNo: 824551161; Manufacturer: Wurth Elektronik
footprint DO-214AB_Bidirectional
pins: 1, 2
